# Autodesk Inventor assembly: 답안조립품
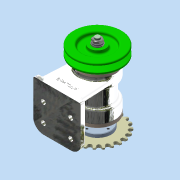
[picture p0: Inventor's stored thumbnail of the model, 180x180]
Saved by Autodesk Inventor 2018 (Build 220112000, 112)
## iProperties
Created: 2024-02
Part Number: 답안조립품
Material: 일반
Document SubType Name: Assembly
Designer: home
Author: home
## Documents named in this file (18)
- C:\Users\kimgi\Desktop\740204V1013\답안조립품.iam
- C:\Users\kimgi\Desktop\740204V1013\본체.ipt
- C:\Users\kimgi\Desktop\740204V1013\깊은 홈 볼 베어링 6204.ipt
- C:\Users\kimgi\Desktop\740204V1013\축.ipt
- C:\Users\kimgi\Desktop\740204V1013\가스켓.ipt
- C:\Users\kimgi\Desktop\740204V1013\커버.ipt
- C:\Users\kimgi\Desktop\740204V1013\오일 실 20 32 5.ipt
- C:\Users\kimgi\Desktop\740204V1013\육각 소켓 머리 볼트 M4 x 10.ipt
- C:\Users\kimgi\Desktop\740204V1013\평행 키 5x5x12.ipt
- C:\Users\kimgi\Desktop\740204V1013\플랜지.ipt
- C:\Users\kimgi\Desktop\740204V1013\앤드 캡.ipt
- C:\Users\kimgi\Desktop\740204V1013\스프로킷.ipt
- C:\Users\kimgi\Desktop\740204V1013\육각 소켓 머리 볼트 M5 x 12.ipt
- C:\Users\kimgi\Desktop\740204V1013\스프링 와셔 M5.ipt
- C:\Users\kimgi\Desktop\740204V1013\V-벨트풀리.ipt
- C:\Users\kimgi\Desktop\740204V1013\평와셔 M10.ipt
- C:\Users\kimgi\Desktop\740204V1013\스프링 와셔 M10.ipt
- C:\Users\kimgi\Desktop\740204V1013\육각 너트 M10x1.ipt
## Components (4 placed, 3 different names)
1. 가스켓:1
2. 가스켓:2
3. 플랜지:1
4. V-벨트풀리:1
